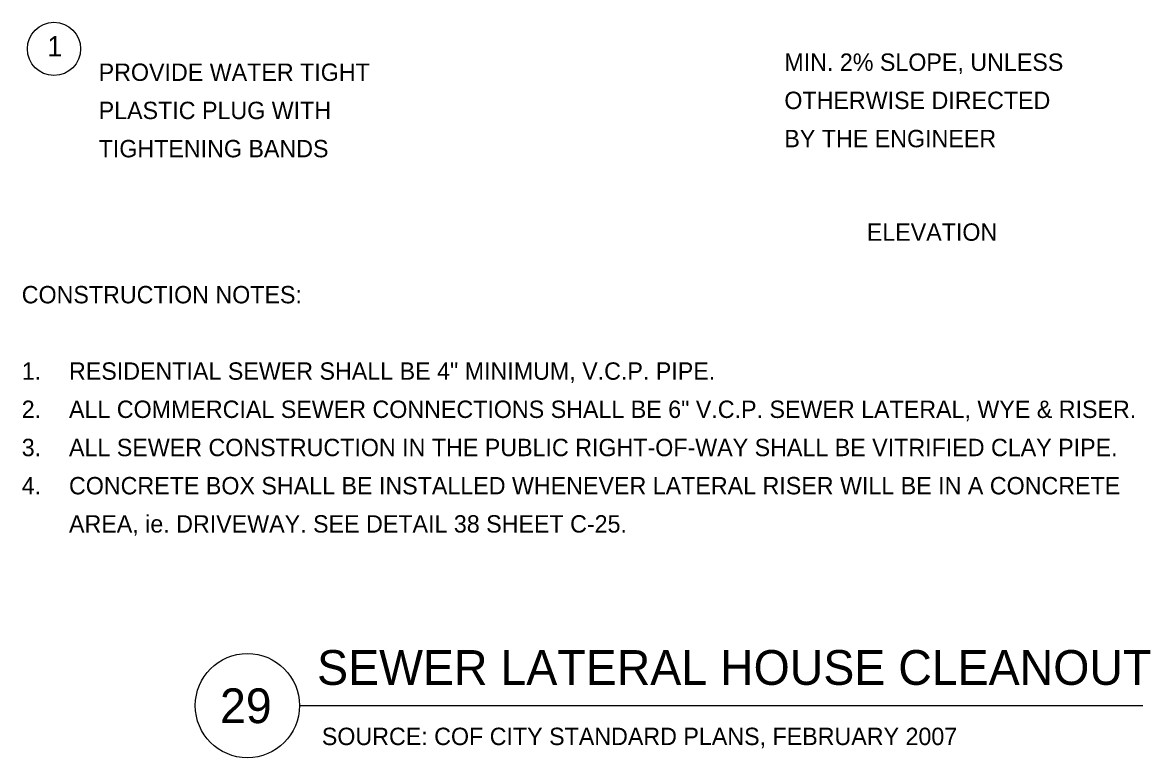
# Model space of a CAD drawing. Extents: x -119017 to -116080, y -104449 to -102845.
# Drawn here: x -116671.9 to -116287.5, y -103751.9 to -103498 of the extents above; entities that cross this region are included whole.
import ezdxf

# ---------------------------------------------------------------- set-up
doc = ezdxf.new("R2010")
doc.units = 0
for name, color, linetype in [('G-MARK', 7, 'Continuous'), ('Misc CnstDet(22)', 7, 'Continuous'), ('Nongeo Data(60)', 7, 'Continuous')]:
    doc.layers.add(name, color=color, linetype=linetype)

msp = doc.modelspace()

# ---------------------------------------------------------------- linework, layer by layer
at = {"layer": 'G-MARK'}
msp.add_circle((-116660.99, -103507.21), 9.18, dxfattribs=at)
at = {"layer": 'Nongeo Data(60)'}
msp.add_line((-116576.21, -103733.93), (-116181.96, -103733.93), dxfattribs=at)
msp.add_circle((-116594.21, -103733.93), 18, dxfattribs=at)

# ---------------------------------------------------------------- texts
at = {"layer": 'Misc CnstDet(22)'}
for s, height, p in [('1', 7, (-116663.31, -103509.8)), ('MIN. 2% SLOPE, UNLESS', 6, (-116408.85, -103514.8)), ('PROVIDE WATER TIGHT', 6, (-116645.57, -103518.27)), ('OTHERWISE DIRECTED', 6, (-116408.85, -103527.99)), ('PLASTIC PLUG WITH', 6, (-116645.57, -103531.46)), ('BY THE ENGINEER', 6, (-116408.85, -103541.18)), ('TIGHTENING BANDS', 6, (-116645.57, -103544.65)), ('ELEVATION', 6, (-116380.39, -103573.46)), ('CONSTRUCTION NOTES:', 6, (-116672.12, -103595.06)), ('1.', 6, (-116672.12, -103621.44)), ('RESIDENTIAL SEWER SHALL BE 4" MINIMUM, V.C.P. PIPE.', 6, (-116655.81, -103621.44)), ('2.', 6, (-116672.12, -103634.63)), ('ALL COMMERCIAL SEWER CONNECTIONS SHALL BE 6" V.C.P. SEWER LATERAL, WYE & RISER.', 6, (-116655.81, -103634.63)), ('3.', 6, (-116672.12, -103647.82)), ('ALL SEWER CONSTRUCTION IN THE PUBLIC RIGHT-OF-WAY SHALL BE VITRIFIED CLAY PIPE.', 6, (-116655.81, -103647.82)), ('4.', 6, (-116672.12, -103661.01)), ('CONCRETE BOX SHALL BE INSTALLED WHENEVER LATERAL RISER WILL BE IN A CONCRETE', 6, (-116655.81, -103661.01)), ('AREA, ie. DRIVEWAY. SEE DETAIL 38 SHEET C-25.', 6, (-116655.81, -103674.2)), ('SEWER LATERAL HOUSE CLEANOUT', 12, (-116570.16, -103726.77)), ('29', 12, (-116603.68, -103739.99)), ('SOURCE: COF CITY STANDARD PLANS, FEBRUARY 2007', 6, (-116568.52, -103747.56))]:
    msp.add_text(s, height=height, dxfattribs=at).set_placement(p)

doc.saveas('drawing.dxf')
